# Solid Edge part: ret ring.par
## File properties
Author: Deepak Maini
Template: normal.par
Last saved by: CADCIM
Revision: 4
Application: Solid Edge
Density: 0.0000078 kg/mm^3
Accuracy: 0.01
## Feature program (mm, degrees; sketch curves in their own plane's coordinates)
sketch for "unnamed RevolvedProtrusion 1" plane through (0, 25.4, 0) normal (0, -1, 0) x-axis (1, 0, 0)
  line (-42.2288, 1.129) -> (-38.3369, 1.129)
  line (-38.3369, 1.129) -> (-38.3369, 0)
  line (-38.3369, 0) -> (-42.2288, 0)
  line (-42.2288, 0) -> (-42.2288, 1.129)
revolve "unnamed RevolvedProtrusion 1" add finite about sketch line (-42.1776, -8.3958) -> (-20.1067, -8.3958)
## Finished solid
Body 1: solid body, 6 faces, 12 edges, 8 vertices.
  Faces by surface: plane 4, cylinder 2
  Edges by curve: line 8, circle 4
Bounding box of the edges (mm): 3.892 x 19.050 x 18.157, from (-42.2288, 15.8752, -17.0282) to (-38.3369, 34.9248, 1.129).
Cylindrical faces by radius (mm): R8.3958 x1, R9.5248 x1
Planar faces by outward normal: +x 1, -x 1, oblique 2
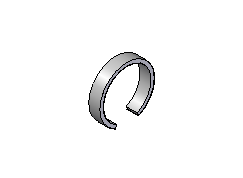
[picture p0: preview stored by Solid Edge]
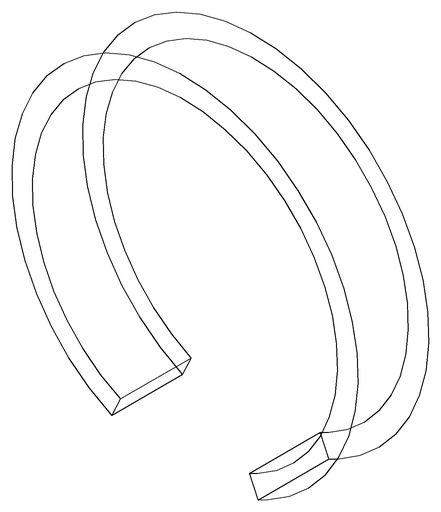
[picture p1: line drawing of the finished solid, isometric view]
